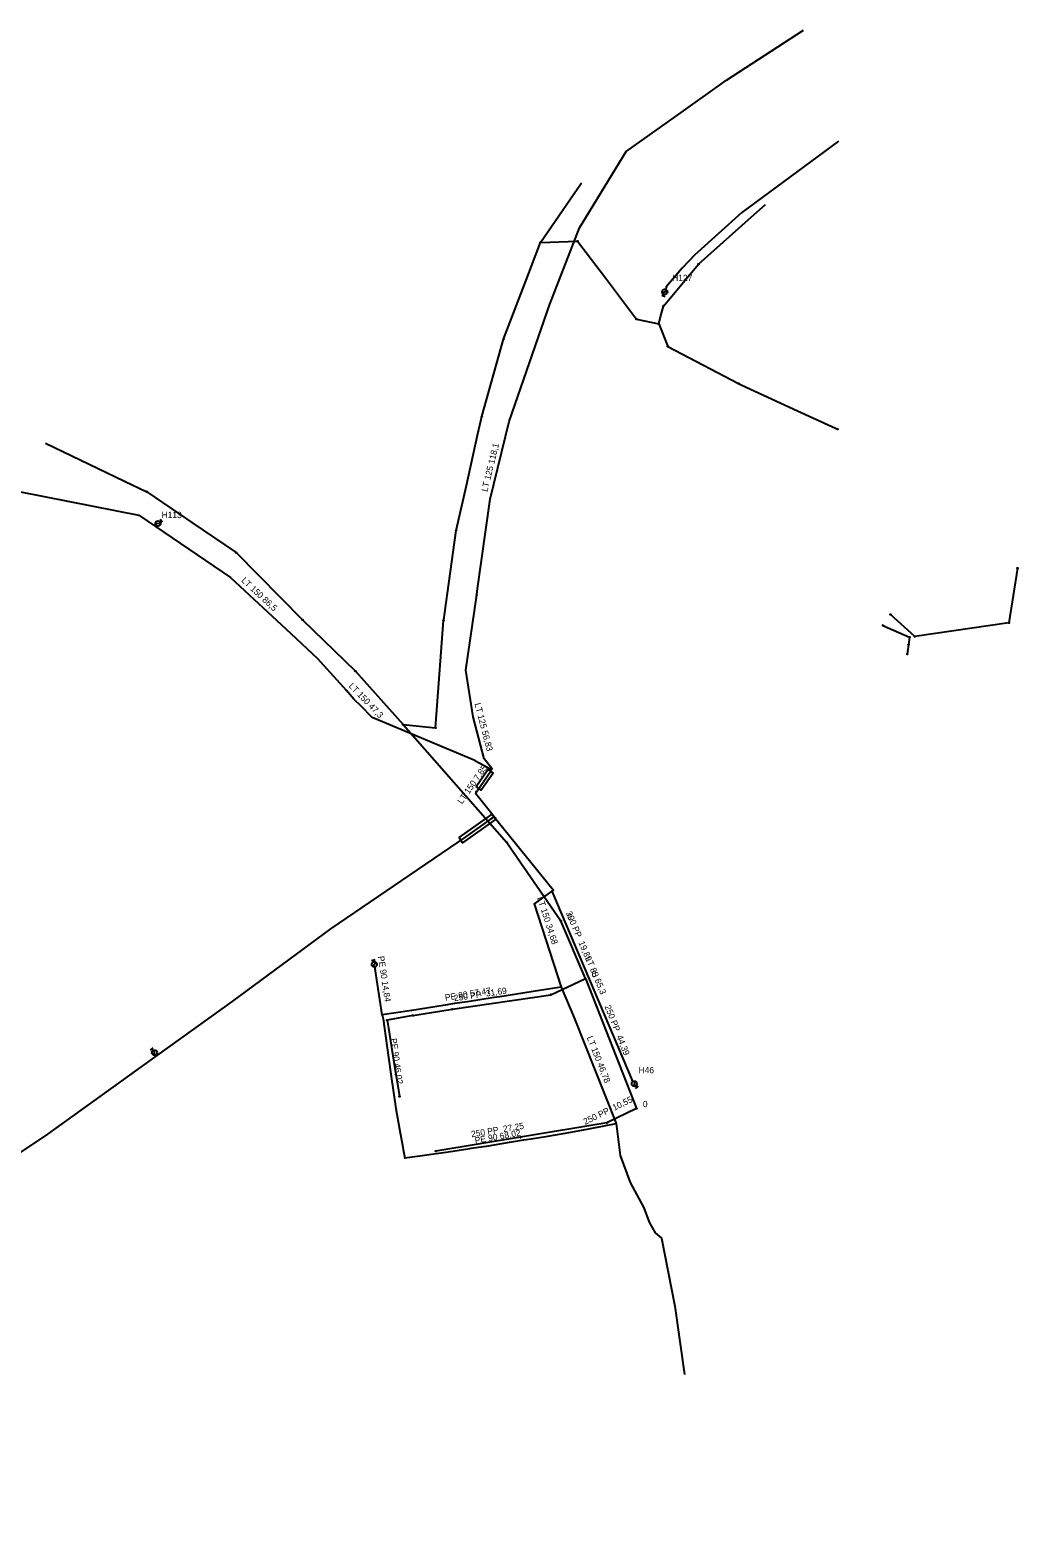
# Model space of a CAD drawing. Extents: x -763749 to -763263, y -1031945 to -1031466.
import ezdxf

# ---------------------------------------------------------------- set-up
doc = ezdxf.new("R2010")
doc.units = 0
for name, color, linetype in [('Vrstva 1', 7, 'Continuous'), ('Vrstva 15', 7, 'Continuous'), ('Vrstva 16', 7, 'Continuous'), ('Vrstva 17', 7, 'Continuous'), ('Vrstva 2', 7, 'Continuous'), ('Vrstva 20', 7, 'Continuous'), ('Vrstva 23', 7, 'Continuous'), ('Vrstva 3', 7, 'Continuous'), ('Vrstva 4', 7, 'Continuous'), ('Vrstva 5', 7, 'Continuous')]:
    doc.layers.add(name, color=color, linetype=linetype)

# ---------------------------------------------------------------- blocks, each defined once
blk = doc.blocks.new('100')
at = {"layer": 'Vrstva 1'}
blk.add_circle((0, 0), 0.127, dxfattribs=at)
blk = doc.blocks.new('160')
at = {"layer": 'Vrstva 1'}
blk.add_circle((0, 0), 0.0458, dxfattribs=at)
blk = doc.blocks.new('133')
at = {"layer": 'Vrstva 1'}
for p, q in [((0.28, 0), (0, 0)), ((0.54, 0.58), (1.7, -0.58)), ((1.94, 0), (2.52, 0)), ((2.52, 0.58), (2.52, -0.58))]:
    blk.add_line(p, q, dxfattribs=at)
blk.add_circle((1.11, 0), 0.825, dxfattribs=at)

msp = doc.modelspace()

# ---------------------------------------------------------------- linework, layer by layer
at = {"layer": 'Vrstva 16'}
for points in [[(-763403.244, -1031532.384), (-763401.961, -1031529.097), (-763387.127, -1031504.801), (-763371.207, -1031493.488), (-763355.287, -1031482.176), (-763330.832, -1031466.284)], [(-763319.689, -1031501.545), (-763350.405, -1031524.248), (-763365.428, -1031537.825), (-763369.399, -1031541.955), (-763374.333, -1031547.789)], [(-763434.658, -1031645.778), (-763434.485, -1031644.578), (-763430.364, -1031615.299), (-763424.309, -1031590.62), (-763411.418, -1031553.308), (-763403.244, -1031532.384)], [(-763602.219, -1031608.587), (-763541.951, -1031620.442)], [(-763541.951, -1031620.442), (-763512.876, -1031640.248), (-763493.715, -1031658.058), (-763485.18, -1031666.004), (-763476.126, -1031676.061)], [(-763429.851, -1031700.877), (-763432.255, -1031697.852), (-763435.73, -1031684.47), (-763438.13, -1031669.719), (-763434.658, -1031645.778)], [(-763435.235, -1031698.327), (-763467.811, -1031684.74), (-763471.328, -1031681.118), (-763473.63, -1031678.84), (-763476.126, -1031676.061)], [(-763435.235, -1031698.327), (-763430.468, -1031700.947)], [(-763434.762, -1031708.284), (-763430.274, -1031701.848)], [(-763430.468, -1031700.947), (-763430.464, -1031700.95), (-763429.992, -1031701.267)], [(-763430.274, -1031701.848), (-763430.132, -1031701.656)], [(-763430.132, -1031701.656), (-763429.992, -1031701.267)], [(-763429.992, -1031701.267), (-763429.851, -1031700.877)], [(-763430.239, -1031714.806), (-763434.935, -1031708.998), (-763434.762, -1031708.284)], [(-763429.087, -1031716.23), (-763430.239, -1031714.806)], [(-763429.087, -1031716.23), (-763429.795, -1031716.731)], [(-763429.087, -1031716.23), (-763428.739, -1031716.66)], [(-763429.795, -1031716.731), (-763438.337, -1031722.775), (-763481.06, -1031751.9), (-763512.18, -1031774.8), (-763536.305, -1031792.137), (-763571.74, -1031817.6), (-763616.5, -1031847.4), (-763628.36, -1031847.48), (-763641.23, -1031854.36), (-763663.29, -1031879.91), (-763687.5, -1031897.56), (-763718.305, -1031921.48), (-763749.109, -1031945.399)], [(-763428.739, -1031716.66), (-763427.776, -1031717.853)], [(-763427.776, -1031717.853), (-763410.221, -1031739.577), (-763410.725, -1031739.935)], [(-763410.725, -1031739.935), (-763416.343, -1031743.922), (-763407.85, -1031770.38)], [(-763410.725, -1031739.935), (-763385.304, -1031800.044)], [(-763464.63, -1031779.24), (-763466.87, -1031764.57)], [(-763407.85, -1031770.38), (-763414.69, -1031771.47), (-763427.35, -1031773.45), (-763429.12, -1031773.72), (-763437.54, -1031775.05), (-763441.67, -1031775.64), (-763444.67, -1031776.14), (-763447.91, -1031776.69), (-763455.24, -1031777.85), (-763456.01, -1031777.97), (-763464.63, -1031779.24)], [(-763407.85, -1031770.38), (-763403.733, -1031780.125), (-763390.36, -1031813.77)], [(-763464.63, -1031779.24), (-763464.4, -1031780.51), (-763463.19, -1031788.97), (-763461.9, -1031798.02), (-763460.34, -1031808.98), (-763459.15, -1031815.55), (-763458.11, -1031821.29), (-763457.98, -1031821.98), (-763457.49, -1031824.69)], [(-763457.49, -1031824.69), (-763451.93, -1031823.89), (-763442.25, -1031822.49), (-763436.79, -1031821.65), (-763436.4, -1031821.59), (-763430.93, -1031820.84), (-763424.19, -1031819.67), (-763419.74, -1031818.95), (-763417.39, -1031818.58), (-763412.06, -1031817.74), (-763404.79, -1031816.51), (-763398.97, -1031815.4), (-763390.36, -1031813.77)], [(-763390.36, -1031813.77), (-763389.059, -1031823.852), (-763385.851, -1031832.526), (-763381.523, -1031840.54), (-763379.838, -1031845.04), (-763377.968, -1031848.465), (-763375.939, -1031850.147), (-763371.667, -1031871.824), (-763368.61, -1031893.515)]]:
    msp.add_lwpolyline(points, dxfattribs=at)
at = {"layer": 'Vrstva 2'}
for points in [[(-763414.347, -1031533.717), (-763401.352, -1031514.769)], [(-763364.216, -1031540.681), (-763347.421, -1031525.757), (-763342.854, -1031521.699)], [(-763426.081, -1031564.522), (-763418.914, -1031545.707), (-763414.347, -1031533.717)], [(-763414.347, -1031533.717), (-763402.599, -1031533.339)], [(-763402.599, -1031533.339), (-763394.077, -1031544.609), (-763383.854, -1031558.129)], [(-763375.325, -1031553.956), (-763368.971, -1031546.364), (-763364.736, -1031541.302), (-763364.216, -1031540.681)], [(-763383.854, -1031558.129), (-763376.828, -1031559.612)], [(-763376.828, -1031559.612), (-763376.242, -1031557.409), (-763375.325, -1031553.956)], [(-763376.828, -1031559.612), (-763373.922, -1031566.844)], [(-763433.005, -1031589.016), (-763426.081, -1031564.522)], [(-763373.922, -1031566.844), (-763351.501, -1031578.58)], [(-763351.501, -1031578.58), (-763350.592, -1031578.998), (-763333.898, -1031586.687), (-763320.691, -1031592.77), (-763319.967, -1031593.104)], [(-763441.138, -1031625.238), (-763437.934, -1031610.97), (-763434.346, -1031594.988), (-763433.005, -1031589.016)], [(-763571.65, -1031597.528), (-763546.51, -1031609.58), (-763539.48, -1031612.956)], [(-763539.48, -1031612.956), (-763526.867, -1031621.545), (-763525.11, -1031622.741), (-763511.051, -1031632.316)], [(-763445.176, -1031653.93), (-763445.033, -1031652.916), (-763444.92, -1031652.114), (-763441.138, -1031625.238)], [(-763511.051, -1031632.316), (-763489.969, -1031653.655)], [(-763262.87, -1031637.29), (-763265.61, -1031654.61)], [(-763489.969, -1031653.655), (-763473.184, -1031669.98)], [(-763447.686, -1031687.986), (-763447.378, -1031683.808), (-763445.176, -1031653.93)], [(-763295.43, -1031658.97), (-763303.18, -1031651.97)], [(-763305.57, -1031655.44), (-763297.15, -1031659.2)], [(-763265.61, -1031654.61), (-763295.43, -1031658.97)], [(-763297.47, -1031661.58), (-763297.85, -1031664.55)], [(-763297.15, -1031659.2), (-763297.47, -1031661.58)], [(-763473.184, -1031669.98), (-763457.995, -1031686.981)], [(-763457.995, -1031686.981), (-763425.031, -1031724.437)], [(-763457.995, -1031686.981), (-763447.686, -1031687.986)], [(-763425.031, -1031724.437), (-763407.897, -1031749.337)], [(-763400.133, -1031767.646), (-763407.897, -1031749.337)], [(-763411.096, -1031772.798), (-763400.133, -1031767.646)], [(-763400.133, -1031767.646), (-763383.845, -1031808.941)], [(-763442.443, -1031777.433), (-763411.096, -1031772.798)], [(-763454.923, -1031779.412), (-763442.443, -1031777.433)], [(-763454.923, -1031779.412), (-763463.115, -1031780.893)], [(-763463.115, -1031780.893), (-763462.705, -1031783.41), (-763460.711, -1031795.649), (-763459.287, -1031804.394), (-763459.169, -1031805.113)], [(-763383.845, -1031808.941), (-763393.336, -1031813.548)], [(-763393.336, -1031813.548), (-763420.778, -1031818.123)], [(-763420.778, -1031818.123), (-763447.669, -1031822.522)]]:
    msp.add_lwpolyline(points, dxfattribs=at)
at = {"layer": 'Vrstva 20'}
for points in [[(-763374.332, -1031547.788), (-763374.545, -1031548.415)], [(-763536.906, -1031623.879), (-763536.752, -1031623.753)], [(-763466.87, -1031764.57), (-763466.94, -1031764.24)], [(-763536.305, -1031792.137), (-763536.336, -1031792.094)], [(-763385.305, -1031800.045), (-763385.225, -1031800.162)]]:
    msp.add_lwpolyline(points, dxfattribs=at)
at = {"layer": 'Vrstva 23'}
for points in [[(-763434.832, -1031706.636), (-763431.094, -1031701.276), (-763429.454, -1031702.42), (-763433.191, -1031707.78), (-763434.832, -1031706.636)], [(-763440.261, -1031722.876), (-763429.683, -1031715.426), (-763428.531, -1031717.062), (-763439.109, -1031724.512), (-763440.261, -1031722.876)]]:
    msp.add_lwpolyline(points, dxfattribs=at)

# ---------------------------------------------------------------- block references
at = {"layer": 'Vrstva 15'}
for p, xscale, yscale, rotation in [((-763403.244, -1031532.384), 0.9999999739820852, 0.9999999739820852, 68.99999941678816), ((-763374.333, -1031547.789), 1.0000000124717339, 1.0000000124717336, -130.0000013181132), ((-763541.951, -1031620.442), 1.025136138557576, 1.025136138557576, -25.2507584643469), ((-763434.658, -1031645.778), 0.9999999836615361, 0.9999999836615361, -98.00000038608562), ((-763476.126, -1031676.061), 1.0000000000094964, 1.0000000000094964, 132.0000013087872), ((-763435.235, -1031698.327), 1.0169562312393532, 1.016956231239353, 153.02398354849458), ((-763430.468, -1031700.947), 1.0072562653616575, 1.0072562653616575, 151.23333487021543), ((-763430.274, -1031701.848), 1.000000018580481, 1.000000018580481, -125.00000023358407), ((-763430.132, -1031701.656), 0.9999999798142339, 0.9999999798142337, -118.00000133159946), ((-763429.992, -1031701.267), 0.999999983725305, 0.999999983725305, -109.00000122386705), ((-763429.851, -1031700.877), 0.9999999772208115, 0.9999999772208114, -79.99999971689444), ((-763434.762, -1031708.284), 0.9999999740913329, 0.9999999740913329, -114.00000060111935), ((-763430.239, -1031714.806), 1.000000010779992, 1.0000000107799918, 128.99999891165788), ((-763429.087, -1031716.23), 1.0098116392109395, 1.0098116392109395, 169.38969821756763), ((-763428.739, -1031716.66), 1.000000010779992, 1.0000000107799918, -51.00000108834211), ((-763429.795, -1031716.731), 1.000000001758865, 1.000000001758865, -144.00000066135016), ((-763427.776, -1031717.853), 1.000000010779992, 1.0000000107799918, 128.99999891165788), ((-763410.725, -1031739.935), 0.999999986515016, 0.9999999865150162, -15.000000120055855), ((-763466.87, -1031764.57), 1.0000000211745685, 1.0000000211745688, 98.99999960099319), ((-763407.85, -1031770.38), 0.9999999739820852, 0.9999999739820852, -68.99999941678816), ((-763464.63, -1031779.24), 1.000000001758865, 1.000000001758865, -35.99999933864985), ((-763385.304, -1031800.044), 1.0000000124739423, 1.000000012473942, 112.99999954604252), ((-763390.36, -1031813.77), 0.999999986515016, 0.9999999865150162, -74.99999987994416), ((-763457.49, -1031824.69), 1.000000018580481, 1.000000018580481, -35.000000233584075)]:
    msp.add_blockref('160', p, dxfattribs=dict(at, xscale=xscale, yscale=yscale, rotation=rotation))
at = {"layer": 'Vrstva 20'}
for p, xscale, yscale, rotation in [((-763374.545, -1031548.415), 1.000000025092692, 1.0000000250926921, -108.00000002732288), ((-763536.751, -1031623.752), 1.0000000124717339, 1.0000000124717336, 40.00000131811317), ((-763466.94, -1031764.24), 1.0000000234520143, 1.0000000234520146, 101.99999938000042), ((-763536.336, -1031792.094), 0.9999999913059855, 0.9999999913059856, 127.00000193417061), ((-763385.224, -1031800.161), 1.000000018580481, 1.000000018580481, -54.99999976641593)]:
    msp.add_blockref('133', p, dxfattribs=dict(at, xscale=xscale, yscale=yscale, rotation=rotation))
at = {"layer": 'Vrstva 4'}
for p, xscale, yscale, rotation in [((-763414.347, -1031533.717), 0.9999999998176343, 0.9999999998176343, -116.9999993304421), ((-763402.599, -1031533.339), 1.0169562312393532, 1.016956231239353, 153.02398354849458), ((-763364.216, -1031540.681), 1.0000000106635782, 1.0000000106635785, -134.00000165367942), ((-763383.854, -1031558.129), 0.9999999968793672, 0.9999999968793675, 147.99999972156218), ((-763375.325, -1031553.956), 0.9999999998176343, 0.9999999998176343, -116.9999993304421), ((-763376.828, -1031559.612), 0.9999999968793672, 0.9999999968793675, -147.99999972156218), ((-763426.081, -1031564.522), 1.000000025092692, 1.0000000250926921, -108.00000002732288), ((-763373.922, -1031566.844), 1.00000000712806, 1.00000000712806, 133.00000056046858), ((-763351.501, -1031578.58), 1.0138865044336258, 1.0138865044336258, 152.43468640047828), ((-763433.005, -1031589.016), 1.0000000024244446, 1.0000000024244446, -104.00000032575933), ((-763319.967, -1031593.104), 1.019856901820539, 1.0198569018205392, -26.393983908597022), ((-763539.48, -1031612.956), 1.0037042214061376, 1.0037042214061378, 150.62079160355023), ((-763441.138, -1031625.238), 0.9999999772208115, 0.9999999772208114, -100.00000028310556), ((-763511.051, -1031632.316), 1.000000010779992, 1.0000000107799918, 141.00000108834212), ((-763262.87, -1031637.29), 0.9999999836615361, 0.9999999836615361, 81.99999961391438), ((-763489.969, -1031653.655), 1.0000000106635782, 1.0000000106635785, 135.99999834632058), ((-763445.176, -1031653.93), 1.0011217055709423, 1.0011217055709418, -96.5826098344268), ((-763303.18, -1031651.97), 1.0000000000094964, 1.0000000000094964, 137.9999986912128), ((-763305.57, -1031655.44), 1.019856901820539, 1.0198569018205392, 153.606016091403), ((-763297.15, -1031659.2), 0.9999999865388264, 0.9999999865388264, -59.99999955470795), ((-763295.43, -1031658.97), 1.0365458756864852, 1.0365458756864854, 158.02850914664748), ((-763265.61, -1031654.61), 0.999999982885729, 0.9999999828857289, -135), ((-763297.47, -1031661.58), 1.000191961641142, 1.000191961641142, -97.08900113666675), ((-763297.85, -1031664.55), 1.000191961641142, 1.000191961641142, -97.08900113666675), ((-763473.184, -1031669.98), 1.0000000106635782, 1.0000000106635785, 134.00000165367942), ((-763457.995, -1031686.981), 1.0000000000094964, 1.0000000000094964, 132.0000013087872), ((-763447.686, -1031687.986), 1.0000000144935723, 1.0000000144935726, -139.00000089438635), ((-763425.031, -1031724.437), 1.000000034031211, 1.0000000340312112, 128.00000040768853), ((-763407.897, -1031749.337), 1.0000000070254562, 1.0000000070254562, 118.99999892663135), ((-763400.133, -1031767.646), 1.0000000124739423, 1.000000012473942, 112.99999954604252), ((-763411.096, -1031772.798), 1.035124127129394, 1.0351241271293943, -157.49634583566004), ((-763442.443, -1031777.433), 1.008377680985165, 1.0083776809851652, -168.37362119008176), ((-763463.115, -1031780.893), 1.000000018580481, 1.000000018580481, 54.99999976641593), ((-763454.923, -1031779.412), 1.0073309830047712, 1.0073309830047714, -167.86109133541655), ((-763459.169, -1031805.113), 0.9999999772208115, 0.9999999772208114, -79.99999971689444), ((-763383.845, -1031808.941), 0.9999999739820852, 0.9999999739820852, -111.00000058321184), ((-763393.336, -1031813.548), 1.033506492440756, 1.033506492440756, -156.95871826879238), ((-763420.778, -1031818.123), 1.0073309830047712, 1.0073309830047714, -167.86109133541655), ((-763447.669, -1031822.522), 1.0073309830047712, 1.0073309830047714, 12.13890866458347)]:
    msp.add_blockref('100', p, dxfattribs=dict(at, xscale=xscale, yscale=yscale, rotation=rotation))

# ---------------------------------------------------------------- texts
at = {"layer": 'Vrstva 17'}
for s, height, rotation, p in [('LT 125 118,1', 1.99999, 76.21, (-763431.271, -1031613.114)), ('LT 150 86,5', 1.99999, 317.09, (-763509.594, -1031641.388)), ('LT 150 47,3', 1.99999, 314.16, (-763475.462, -1031674.851)), ('LT 125 56,83', 1.99999, 284.56, (-763435.353, -1031680.356)), ('LT 150 7,85', 1.99999, 55.11, (-763439.329, -1031712.386)), ('LT 150 34,68', 1.99999, 287.8, (-763415.486, -1031742.015)), ('PE 90 14,84', 1.99999, 278.68, (-763466.051, -1031760.661)), ('LT 80 65,3', 2, 292.92, (-763400.23, -1031761.155)), ('PE 90 57,47', 1.99999, 8.98, (-763444.579, -1031774.745)), ('PE 90 46,02', 1.99999, 278.11, (-763462.087, -1031786.791)), ('LT 150 46,78', 1.99999, 291.68, (-763399.735, -1031786.394)), ('PE 90 68,02', 1.99999, 9.85, (-763435.069, -1031820.138))]:
    msp.add_text(s, height=height, rotation=rotation, dxfattribs=at).set_placement(p)
at = {"layer": 'Vrstva 20'}
for s, p in [('H127', (-763372.545, -1031546.015)), ('H113', (-763534.751, -1031621.352)), ('H46', (-763383.224, -1031797.761))]:
    msp.add_text(s, height=2, dxfattribs=at).set_placement(p)
at = {"layer": 'Vrstva 3'}
for s, rotation, p in [('300 PP  19,89', 292.98, (-763406.374, -1031746.783)), ('250 PP  31,69', 8.41, (-763441.746, -1031774.902)), ('250 PP  44,39', 291.53, (-763394.05, -1031776.53)), ('250 PP  10,55', 25.89, (-763400.164, -1031814.194)), ('250 PP  27,25', 9.29, (-763436.24, -1031818.128))]:
    msp.add_text(s, height=1.99999, rotation=rotation, dxfattribs=at).set_placement(p)
at = {"layer": 'Vrstva 5'}
for p in [(-763405.897, -1031748.937), (-763398.133, -1031767.246), (-763381.845, -1031808.541)]:
    msp.add_text('0 ', height=2, dxfattribs=at).set_placement(p)

doc.saveas('drawing.dxf')
